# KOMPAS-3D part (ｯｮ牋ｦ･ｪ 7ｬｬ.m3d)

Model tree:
1. Эскиз:1
2. Операция выдавливания:1
     Расстояние 1 = 8
3. Эскиз:2
4. Операция выдавливания:2
     Расстояние 1 = 1
5. Эскиз:3
6. Операция выдавливания:3
     Расстояние 1 = 2.5; Угол 1 = 8
7. Эскиз:4
8. Вырезать элемент выдавливания:1
     Расстояние 1 = 20
9. Эскиз:5
10. Вырезать элемент выдавливания:2
     Расстояние 1 = 3; Угол 1 = 19
11. Скругление:1
     Радиус = 1
12. Скругление:2
     Радиус = 1
13. Скругление:3
     Радиус = 1
14. Эскиз:6
15. Эскиз:7
16. Вырезать элемент выдавливания:3
     Расстояние 2 = 30; Расстояние 1 = 60
17. Эскиз:8
18. Вырезать элемент выдавливания:4
     Расстояние 2 = 30; Расстояние 1 = 60
19. Эскиз:9
20. Операция выдавливания:4
     Расстояние 1 = 10; Расстояние 2 = 62
21. Эскиз:10
22. Вырезать элемент выдавливания:5
     Расстояние 2 = 30; Расстояние 1 = 60
23. Скругление:4
     Радиус = 2
24. Скругление:5
     Радиус = 2
25. Эскиз:11
26. Вырезать элемент выдавливания:6
     Расстояние 1 = 10
27. Эскиз:12
28. Вырезать элемент выдавливания:7
     Расстояние 1 = 2.5; Угол 1 = 3
29. Эскиз:13
30. Вырезать элемент выдавливания:8
     Расстояние 2 = 40; Расстояние 1 = 30
31. Эскиз:14
32. Операция выдавливания:5
     Расстояние 1 = 10
33. Операция выдавливания:6
     Расстояние 1 = 2.5; Расстояние 2 = 5.94316
34. Эскиз:15
35. Вырезать элемент выдавливания:9
     Расстояние 1 = 20
36. Эскиз:16
37. Вырезать элемент выдавливания:10
     Расстояние 1 = 10
